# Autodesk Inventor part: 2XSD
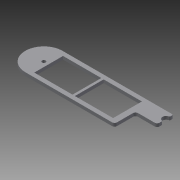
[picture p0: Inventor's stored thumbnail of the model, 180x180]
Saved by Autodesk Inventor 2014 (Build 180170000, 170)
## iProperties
Created: 2015-01
Part Number: 2XSD
Material: Generic
Document SubType Name: Modeling
Designer: Drano
Density: 1 g/cm^3
Appearance: Default
Author: Drano
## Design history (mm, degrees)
sketch "Sketch1"
  geometry: L1 (-32.94, -14.246)-(39.56, -14.246); L2 (-32.94, 16.754)-(44.06, 16.754); L3 (-28.94, -10.746)-(2.96, -10.746); L4 (2.96, -10.746)-(2.96, 13.254); L5 (-28.94, 13.254)-(2.96, 13.254); L6 (-28.94, -10.746)-(-28.94, 13.254); L7 (4.96, -10.746)-(36.86, -10.746); L8 (36.86, -10.746)-(36.86, 13.254); L9 (4.96, 13.254)-(36.86, 13.254); L10 (4.96, -10.746)-(4.96, 13.254); L11 (44.06, 16.754)-(58.56, 16.754); L12 (59.56, 5.254)-(59.56, 6.881); L13 (59.56, 14.627)-(59.56, 15.754); L14 (43.56, 3.254)-(57.56, 3.254); L15 (41.56, -12.246)-(41.56, 1.254); C1 r 1.5 at (-32.94, 1.254); A1 r 2 centre (39.56, -12.246) between (39.56, -14.246) and (41.56, -12.246); A2 r 15.5 centre (-32.94, 1.254) between (-32.94, 16.754) and (-32.94, -14.246); A3 r 1 centre (58.56, 15.754) between (59.56, 15.754) and (58.56, 16.754); A4 r 2 centre (57.56, 5.254) between (57.56, 3.254) and (59.56, 5.254); A5 r 3 centre (59.56, 10.754) between (58.81, 13.659) and (58.81, 7.85); A6 r 1 centre (58.56, 6.881) between (59.56, 6.881) and (58.81, 7.85); A7 r 1 centre (58.56, 14.627) between (58.81, 13.659) and (59.56, 14.627); A8 r 2 centre (43.56, 1.254) between (43.56, 3.254) and (41.56, 1.254); 1 further point
  constraints: 30 end point, 16 point on circle, 9 centre point
extrude "Extrusion1" new body sketch "Sketch1" distance "d0" = 2.7; taper "d1" = 0 deg
body "Solid1"
